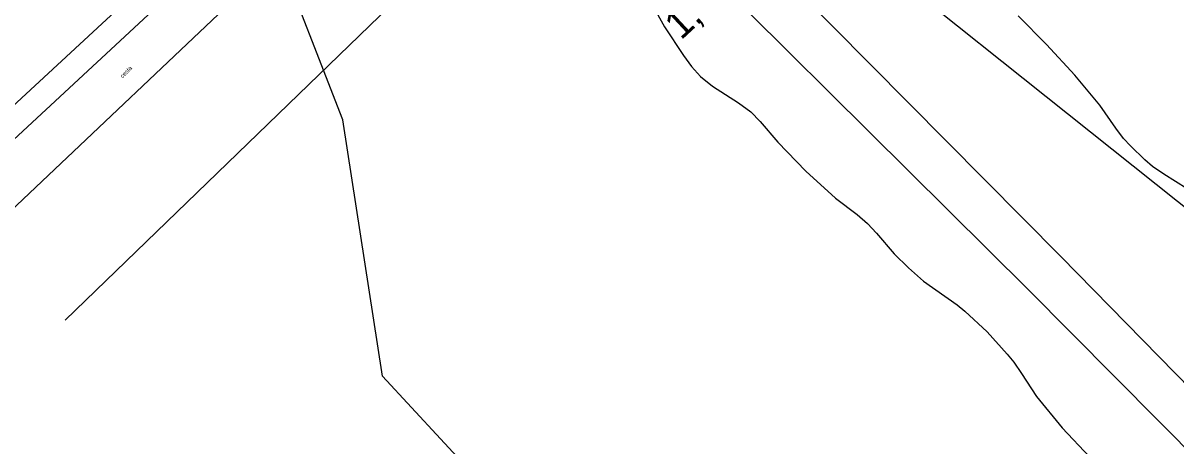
# Model space of a CAD drawing. Extents: x -737422 to -734235, y -1145631 to -1142623.
# Drawn here: x -737309 to -737228.2, y -1144541.9 to -1144512.2 of the extents above; entities that cross this region are included whole.
import ezdxf

# ---------------------------------------------------------------- set-up
doc = ezdxf.new("R2010")
doc.units = 0
for name, color, linetype in [('Vrstva 1', 7, 'Continuous'), ('Vrstva 20', 7, 'Continuous'), ('Vrstva 21', 7, 'Continuous'), ('Vrstva 22', 7, 'Continuous'), ('Vrstva 3', 7, 'Continuous'), ('Vrstva 30', 7, 'Continuous'), ('Vrstva 7', 7, 'Continuous'), ('Vrstva 8', 7, 'Continuous')]:
    doc.layers.add(name, color=color, linetype=linetype)

msp = doc.modelspace()

# ---------------------------------------------------------------- linework, layer by layer
at = {"layer": 'Vrstva 1'}
for points in [[(-737264.535, -1144511.61), (-737264.063, -1144512.471), (-737262.729, -1144514.473)], [(-737227.424, -1144523.837), (-737229.068, -1144522.814), (-737229.851, -1144522.264), (-737230.39, -1144521.802), (-737231.405, -1144520.818), (-737231.883, -1144520.296), (-737232.436, -1144519.568), (-737233.549, -1144517.961), (-737235.291, -1144515.863), (-737237.293, -1144513.706), (-737239.283, -1144511.696)], [(-737262.729, -1144514.473), (-737262.174, -1144515.251), (-737261.546, -1144515.957), (-737260.715, -1144516.626), (-737258.882, -1144517.794), (-737258.026, -1144518.438), (-737257.361, -1144519.107), (-737256.135, -1144520.547), (-737254.17, -1144522.582), (-737252.071, -1144524.483), (-737250.561, -1144525.64), (-737249.843, -1144526.255), (-737249.201, -1144526.947), (-737247.979, -1144528.392), (-737246.961, -1144529.374), (-737245.905, -1144530.317), (-737243.561, -1144531.973), (-737243.018, -1144532.43), (-737241.451, -1144533.864), (-737240.036, -1144535.448), (-737239.587, -1144535.999), (-737239.042, -1144536.787), (-737237.985, -1144538.398), (-737236.187, -1144540.6), (-737234.26, -1144542.673)]]:
    msp.add_lwpolyline(points, dxfattribs=at)
at = {"layer": 'Vrstva 20'}
for points in [[(-737294.75, -1144506.48), (-737313, -1144523.4)], [(-737310.83, -1144526.24), (-737291.82, -1144508.21)]]:
    msp.add_lwpolyline(points, dxfattribs=at)
at = {"layer": 'Vrstva 21'}
msp.add_lwpolyline([(-737313.87, -1144521.83), (-737296.01, -1144505.26)], dxfattribs=at)
at = {"layer": 'Vrstva 3'}
for points in [[(-737149.87, -1144615.18), (-737173.05, -1144592.09), (-737196.01, -1144569.22), (-737219.08, -1144546.16), (-737236.29, -1144528.58), (-737268.32, -1144496.21)], [(-737269.31, -1144500.37), (-737238.57, -1144530.9), (-737208.12, -1144561.61), (-737164.21, -1144604.89)]]:
    msp.add_lwpolyline(points, dxfattribs=at)
at = {"layer": 'Vrstva 30'}
for points in [[(-737188, -1144636), (-737197, -1144643), (-737202, -1144646), (-737204, -1144644), (-737206, -1144641), (-737204, -1144635), (-737200, -1144631), (-737189.99, -1144614.66), (-737189.99, -1144604.28), (-737198.3, -1144596.67), (-737223.92, -1144569.68), (-737241.92, -1144562.07), (-737269.62, -1144552.38), (-737283.85, -1144536.98), (-737286.62, -1144518.99), (-737291.47, -1144506.53), (-737308.08, -1144494.77), (-737319.86, -1144496.15), (-737328.86, -1144513.45), (-737338.55, -1144529.37), (-737347.55, -1144528.68), (-737350.32, -1144520.38), (-737350.102, -1144519.784)], [(-736663.466, -1144596.518), (-736686.22, -1144595.94), (-736731.65, -1144659.43), (-736780.67, -1144680.24), (-736852.36, -1144681.97), (-737002.86, -1144640.9), (-737132.32, -1144601.14), (-737251.24, -1144506.25)]]:
    msp.add_lwpolyline(points, dxfattribs=at)
at = {"layer": 'Vrstva 8'}
msp.add_lwpolyline([(-737306.1, -1144533.06), (-737232.13, -1144461.41)], dxfattribs=at)

# ---------------------------------------------------------------- texts
at = {"layer": 'Vrstva 22'}
msp.add_text('cesta', height=0.3, rotation=45.52, dxfattribs=at).set_placement((-737302.07, -1144516.09))
at = {"layer": 'Vrstva 7'}
msp.add_text('1,8', height=2, rotation=42.828, dxfattribs=at).set_placement((-737262.92, -1144513.44))

doc.saveas('drawing.dxf')
